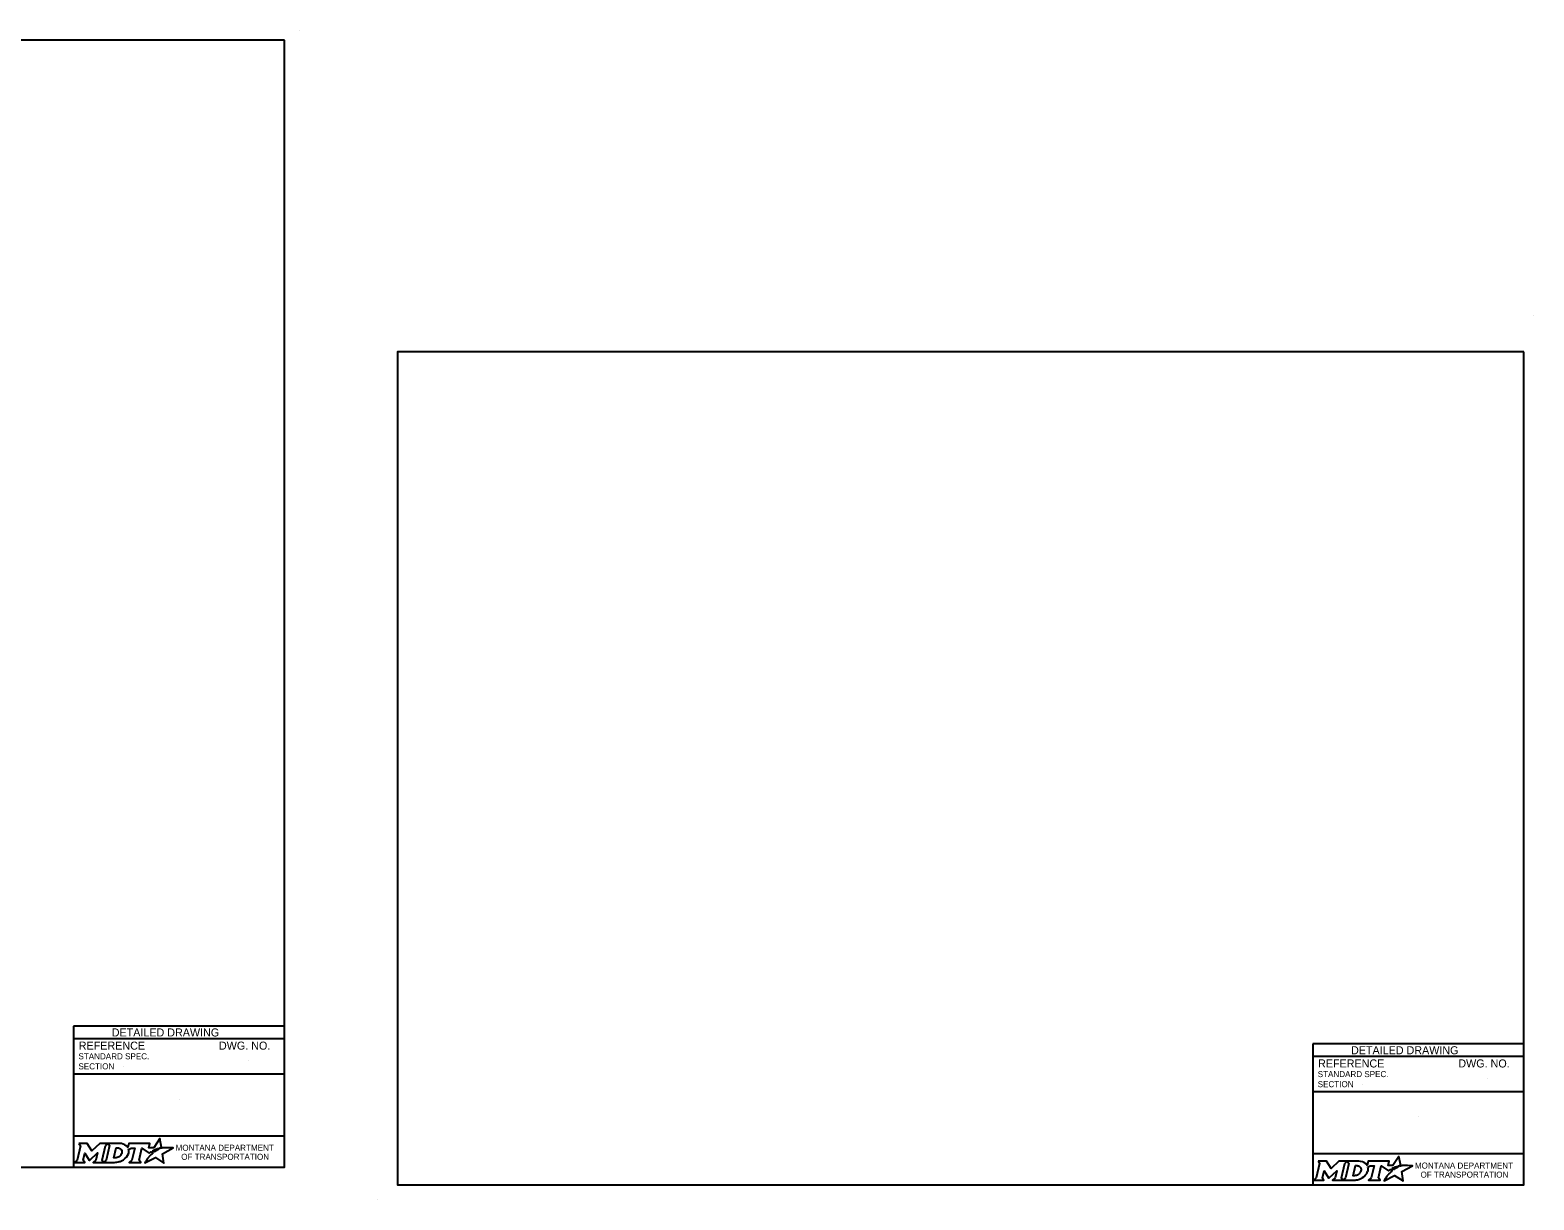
# Model space of a CAD drawing. Extents: x 49991.4 to 50021, y 49987.6 to 50011.4.
# Drawn here: x 50006.08 to 50021.04, y 49999.74 to 50011.36 of the extents above; entities that cross this region are included whole.
import ezdxf

# ---------------------------------------------------------------- set-up
doc = ezdxf.new("R2010")
doc.units = 0
for name, color, linetype in [('Default', 7, 'Continuous'), ('Level 1', 7, 'Continuous'), ('Level 2', 7, 'Continuous'), ('Level 4', 7, 'Continuous')]:
    doc.layers.add(name, color=color, linetype=linetype)

msp = doc.modelspace()

# ---------------------------------------------------------------- linework, layer by layer
at = {"layer": 'Default'}
for points in [[(50018.893, 50000.121), (50018.907, 50000.097), (50018.874, 49999.954), (50018.848, 49999.931), (50018.95, 49999.931), (50018.936, 49999.954), (50018.952, 50000.024), (50018.996, 49999.955), (50019.002, 49999.955), (50019.077, 50000.025), (50019.06, 49999.954), (50019.035, 49999.932), (50019.137, 49999.932), (50019.123, 49999.955), (50019.156, 50000.097)], [(50019.156, 50000.097), (50019.182, 50000.121), (50019.099, 50000.121), (50019.02, 50000.048), (50018.975, 50000.12), (50018.893, 50000.121)], [(50019.295, 50000.121), (50019.182, 50000.121), (50019.196, 50000.098), (50019.163, 49999.954), (50019.137, 49999.932), (50019.248, 49999.932)], [(50019.319, 50000.034), (50019.318, 50000.026), (50019.315, 50000.017), (50019.311, 50000.008), (50019.305, 50000.001), (50019.299, 49999.994), (50019.291, 49999.988), (50019.282, 49999.983), (50019.273, 49999.979), (50019.264, 49999.977), (50019.255, 49999.976), (50019.239, 49999.976), (50019.263, 50000.076), (50019.279, 50000.076), (50019.286, 50000.075), (50019.294, 50000.073), (50019.301, 50000.07), (50019.307, 50000.066), (50019.311, 50000.061), (50019.315, 50000.055), (50019.318, 50000.049), (50019.319, 50000.042), (50019.32, 50000.038), (50019.319, 50000.034)], [(50019.7, 50000.068), (50019.69, 50000.074), (50019.702, 50000.076), (50019.713, 50000.078), (50019.696, 50000.168), (50019.636, 50000.077), (50019.589, 50000.076), (50019.599, 50000.12), (50019.39, 50000.121), (50019.38, 50000.078), (50019.374, 50000.086)], [(50019.387, 50000.062), (50019.411, 50000.075), (50019.448, 50000.075), (50019.42, 49999.954), (50019.392, 49999.931), (50019.508, 49999.931), (50019.491, 49999.954), (50019.52, 50000.075), (50019.591, 50000.023), (50019.612, 50000.038), (50019.632, 50000.027)], [(50019.576, 49999.971), (50019.561, 49999.947), (50019.556, 49999.939), (50019.55, 49999.931), (50019.548, 49999.926), (50019.653, 49999.979), (50019.737, 49999.924), (50019.724, 50000.017), (50019.831, 50000.075), (50019.782, 50000.076), (50019.751, 50000.077), (50019.731, 50000.077), (50019.724, 50000.075), (50019.719, 50000.074), (50019.711, 50000.072), (50019.7, 50000.068)], [(50019.65, 50000.04), (50019.648, 50000.039), (50019.629, 50000.048), (50019.639, 50000.054), (50019.644, 50000.056), (50019.652, 50000.06), (50019.658, 50000.063), (50019.666, 50000.066), (50019.673, 50000.068), (50019.685, 50000.061), (50019.681, 50000.059), (50019.676, 50000.056), (50019.672, 50000.054), (50019.667, 50000.051), (50019.665, 50000.05), (50019.662, 50000.049), (50019.66, 50000.047), (50019.658, 50000.046), (50019.655, 50000.044), (50019.652, 50000.042), (50019.65, 50000.04)], [(50019.293, 49999.939), (50019.302, 49999.942), (50019.315, 49999.947), (50019.335, 49999.958)], [(50019.59, 49999.987), (50019.59, 49999.987)]]:
    msp.add_lwpolyline(points, dxfattribs=at)
for centre, radius, start, end in [((50019.274, 50000.059), 0.118, 300.9103, 339.1383), ((50019.319, 50000.042), 0.0709, 339.5329, 15.8582)]:
    msp.add_arc(centre, radius, start, end, dxfattribs=at)
for centre, major_axis, ratio, start_param, end_param in [((50019.293, 50000.073), (0.0834, -0.0037), 0.568097, 0.61298, 1.570796), ((50019.349, 50000.081), (0.0361, -0.0295), 0.469099, 1.225588, 1.570796), ((50019.248, 50000.08), (0, 0.148), 0.987302, 3.139398, 3.456847), ((50019.583, 49999.979), (-0.00694, -0.00806), 0.008222, 0, 3.137361), ((50019.6, 49999.997), (-0.0098, -0.0102), 0.016458, 3.141593, 6.279097), ((50019.621, 50000.017), (-0.0112, -0.0097), 0.021651, 3.157348, 6.283185)]:
    msp.add_ellipse(centre, major_axis=major_axis, ratio=ratio, start_param=start_param, end_param=end_param, dxfattribs=at)
at = {"layer": 'Level 1'}
for p, q in [((50008.765, 50011.363), (50008.765, 50011.363)), ((50021.038, 50008.524), (50021.038, 50008.524)), ((50009.537, 49999.736), (50009.537, 49999.736))]:
    msp.add_line(p, q, dxfattribs=at)
for points in [[(50008.615, 50011.263), (50000.336, 50011.263), (50000.336, 50000.062), (50008.615, 50000.062)], [(50020.938, 50008.165), (50009.737, 50008.165), (50009.737, 49999.886), (50020.938, 49999.886)]]:
    msp.add_lwpolyline(points, close=True, dxfattribs=at)
at = {"layer": 'Level 2'}
for p, q in [((50008.615, 50001.462), (50006.515, 50001.462)), ((50006.515, 50001.462), (50006.515, 50000.062)), ((50008.615, 50001.337), (50006.515, 50001.337)), ((50008.251, 50001.122), (50008.251, 50001.122)), ((50008.615, 50000.987), (50006.515, 50000.987)), ((50007.009, 50001.063), (50007.009, 50001.063)), ((50007.565, 50000.738), (50007.565, 50000.738)), ((50008.615, 50000.369), (50006.515, 50000.369))]:
    msp.add_line(p, q, dxfattribs=at)
for points in [[(50006.57, 50000.297), (50006.584, 50000.274), (50006.551, 50000.131), (50006.525, 50000.108), (50006.627, 50000.108), (50006.613, 50000.131), (50006.629, 50000.201), (50006.673, 50000.132), (50006.678, 50000.132), (50006.753, 50000.202), (50006.737, 50000.13), (50006.712, 50000.108), (50006.814, 50000.108), (50006.8, 50000.132), (50006.833, 50000.274)], [(50006.833, 50000.274), (50006.859, 50000.297), (50006.776, 50000.297), (50006.697, 50000.224), (50006.652, 50000.297), (50006.57, 50000.297)], [(50006.972, 50000.297), (50006.859, 50000.297), (50006.873, 50000.275), (50006.839, 50000.131), (50006.814, 50000.108), (50006.925, 50000.108)], [(50006.996, 50000.211), (50006.995, 50000.203), (50006.992, 50000.193), (50006.988, 50000.185), (50006.982, 50000.178), (50006.976, 50000.171), (50006.968, 50000.164), (50006.959, 50000.16), (50006.95, 50000.156), (50006.941, 50000.154), (50006.932, 50000.153), (50006.916, 50000.153), (50006.94, 50000.253), (50006.956, 50000.253), (50006.963, 50000.252), (50006.971, 50000.25), (50006.977, 50000.247), (50006.983, 50000.243), (50006.988, 50000.238), (50006.992, 50000.232), (50006.995, 50000.226), (50006.996, 50000.218), (50006.996, 50000.215), (50006.996, 50000.211)], [(50007.377, 50000.245), (50007.367, 50000.25), (50007.378, 50000.253), (50007.39, 50000.255), (50007.373, 50000.345), (50007.313, 50000.254), (50007.266, 50000.253), (50007.276, 50000.297), (50007.067, 50000.297), (50007.057, 50000.255), (50007.051, 50000.263)], [(50007.064, 50000.238), (50007.088, 50000.251), (50007.125, 50000.251), (50007.097, 50000.131), (50007.069, 50000.108), (50007.185, 50000.108), (50007.168, 50000.131), (50007.196, 50000.251), (50007.268, 50000.2), (50007.289, 50000.215), (50007.309, 50000.204)], [(50007.253, 50000.148), (50007.237, 50000.124), (50007.233, 50000.116), (50007.227, 50000.107), (50007.225, 50000.103), (50007.33, 50000.156), (50007.414, 50000.101), (50007.401, 50000.194), (50007.508, 50000.252), (50007.458, 50000.253), (50007.428, 50000.253), (50007.407, 50000.254), (50007.401, 50000.252), (50007.396, 50000.251), (50007.387, 50000.249), (50007.377, 50000.245)], [(50007.327, 50000.217), (50007.324, 50000.215), (50007.306, 50000.225), (50007.316, 50000.231), (50007.32, 50000.233), (50007.329, 50000.237), (50007.335, 50000.239), (50007.343, 50000.243), (50007.35, 50000.245), (50007.362, 50000.238), (50007.358, 50000.236), (50007.353, 50000.233), (50007.349, 50000.231), (50007.344, 50000.228), (50007.342, 50000.227), (50007.339, 50000.225), (50007.337, 50000.224), (50007.334, 50000.222), (50007.332, 50000.221), (50007.329, 50000.219), (50007.327, 50000.217)], [(50006.97, 50000.116), (50006.979, 50000.118), (50006.992, 50000.124), (50007.012, 50000.135)], [(50007.267, 50000.164), (50007.267, 50000.164)]]:
    msp.add_lwpolyline(points, dxfattribs=at)
for centre, radius, start, end in [((50006.995, 50000.219), 0.0709, 339.5329, 15.8582), ((50006.951, 50000.236), 0.118, 300.9103, 339.1383)]:
    msp.add_arc(centre, radius, start, end, dxfattribs=at)
for centre, major_axis, ratio, start_param, end_param in [((50006.97, 50000.25), (0.0834, -0.0037), 0.568097, 0.61298, 1.570796), ((50007.026, 50000.257), (0.0361, -0.0295), 0.469099, 1.225588, 1.570796), ((50006.925, 50000.257), (0, 0.148), 0.987302, 3.139398, 3.456847), ((50007.26, 50000.156), (-0.00694, -0.00806), 0.008222, 0, 3.137361), ((50007.276, 50000.174), (-0.0098, -0.0102), 0.016458, 3.141593, 6.279097), ((50007.297, 50000.194), (-0.0112, -0.0097), 0.021651, 3.157348, 6.283185)]:
    msp.add_ellipse(centre, major_axis=major_axis, ratio=ratio, start_param=start_param, end_param=end_param, dxfattribs=at)
at = {"layer": 'Level 4'}
for p, q in [((50020.938, 50001.286), (50018.838, 50001.286)), ((50018.838, 50001.286), (50018.838, 49999.886)), ((50020.938, 50001.161), (50018.838, 50001.161)), ((50019.332, 50000.886), (50019.332, 50000.886)), ((50020.574, 50000.946), (50020.574, 50000.946)), ((50020.938, 50000.811), (50018.838, 50000.811)), ((50019.888, 50000.562), (50019.888, 50000.562)), ((50020.938, 50000.193), (50018.838, 50000.193))]:
    msp.add_line(p, q, dxfattribs=at)

# ---------------------------------------------------------------- texts
at = {"layer": 'Default'}
for s, p in [('MONTANA DEPARTMENT', (50019.854, 50000.047)), ('OF TRANSPORTATION', (50019.91, 49999.957))]:
    msp.add_text(s, height=0.06, dxfattribs=at).set_placement(p)
at = {"layer": 'Level 2'}
for s, height, p in [('DETAILED DRAWING', 0.0799, (50006.896, 50001.36)), ('REFERENCE', 0.08, (50006.568, 50001.229)), ('DWG. NO.', 0.08, (50007.962, 50001.229)), ('STANDARD SPEC.', 0.06, (50006.565, 50001.133)), ('SECTION', 0.06, (50006.565, 50001.033)), ('MONTANA DEPARTMENT', 0.06, (50007.531, 50000.224)), ('OF TRANSPORTATION', 0.06, (50007.587, 50000.134))]:
    msp.add_text(s, height=height, dxfattribs=at).set_placement(p)
at = {"layer": 'Level 4'}
for s, height, p in [('DETAILED DRAWING', 0.0799, (50019.219, 50001.183)), ('REFERENCE', 0.08, (50018.891, 50001.052)), ('DWG. NO.', 0.08, (50020.286, 50001.052)), ('STANDARD SPEC.', 0.06, (50018.888, 50000.956)), ('SECTION', 0.06, (50018.888, 50000.856))]:
    msp.add_text(s, height=height, dxfattribs=at).set_placement(p)

doc.saveas('drawing.dxf')
